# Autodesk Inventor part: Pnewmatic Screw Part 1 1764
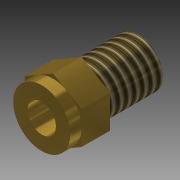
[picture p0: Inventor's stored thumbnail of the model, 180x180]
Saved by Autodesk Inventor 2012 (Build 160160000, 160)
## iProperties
Created: 2010-02
Part Number: Pnewmatic Screw Part 1 1764
Document SubType Name: Modeling
Designer: clee1
Density: 1 g/cm^3
Material: Default
Author: clee1
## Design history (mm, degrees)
sketch "Sketch1"
  geometry: C1 r 5.397 at (0, 0); 1 further point
  constraints: 1 centre point, 1 coincident
  dimensions: "d0" = 10.795 diameter of C1
extrude "Extrusion1" new body sketch "Sketch1" distance "d1" = 12.7; taper "d2" = 0 deg
thread "Thread1" dims "d3" = 25.4, "d4" = 0
sketch "Sketch2"
  geometry: L1 (0, 7.332)-(6.35, 3.666); L2 (6.35, 3.666)-(6.35, -3.666); L3 (6.35, -3.666)-(0, -7.332); L4 (0, -7.332)-(-6.35, -3.666); L5 (-6.35, -3.666)-(-6.35, 3.666); L6 (-6.35, 3.666)-(0, 7.332); C1 r 5.397 at (0, 0) reference; 1 further point
  constraints: 12 end point, 13 other
  dimensions: "d5" = 12.7 distance between parallel lines of L2 L5; "d6" = 0 distance of point (0, 0) C1.centre
extrude "Extrusion2" join sketch "Sketch2" distance "d7" = 6.35; taper "d8" = 0 deg
sketch "Sketch3"
  geometry: L1 (0, 7.332)-(6.35, 3.666) reference; C1 r 6.35 at (0, 0); 1 further point
  constraints: 1 centre point, 1 coincident, 1 tangent
extrude "Extrusion3" join sketch "Sketch3" distance "d9" = 2.54; taper "d10" = 0 deg
sketch "Sketch4"
  geometry: C1 r 6.35 at (0, 0) reference; C2 r 3.175 at (0, 0)
  constraints: 1 centre point, 1 coincident
  dimensions: "d11" = 6.35 diameter of C2
extrude "Extrusion4" cut sketch "Sketch4" stored distance "d12" = 2.54; taper "d13" = 0 deg
body "Solid1"
